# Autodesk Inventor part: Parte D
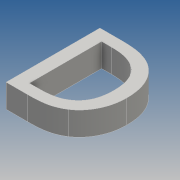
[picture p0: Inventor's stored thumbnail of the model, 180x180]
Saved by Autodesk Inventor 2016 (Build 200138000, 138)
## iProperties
Created: 2015-08
Part Number: Parte D
Material: Generic
Document SubType Name: Modeling
Designer: julian.chica
Density: 1 g/cm^3
Appearance: Default
Author: julian.chica
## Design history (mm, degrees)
sketch "Sketch1"
  geometry: L1 (-8.338, 20.108)-(8.338, 20.108); L2 (8.338, 20.108)-(8.338, 0); L3 (8.338, 0)-(-8.338, 0); L4 (-8.338, 0)-(-8.338, 20.108); 2 further points
  constraints: 1 coincident, 1 midpoint, 2 other
extrude "Extrusion1" new body sketch "Sketch1" distance "d1" = 5; taper "d2" = 0 deg
body "Solid1"
